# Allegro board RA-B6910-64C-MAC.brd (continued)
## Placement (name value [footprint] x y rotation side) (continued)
C1262  10uF/6.3V  [C0402]  211.55 147.82 180 bottom
C1263  10uF/6.3V  [C0402]  211.55 146.82 0 bottom
C1264  10uF/6.3V  [C0402]  211.55 145.82 0 bottom
C1265  10uF/6.3V  [C0402]  211.55 144.82 0 bottom
C1266  10uF/6.3V  [C0402]  211.55 143.82 180 bottom
C1267  10uF/6.3V  [C0402]  211.55 142.82 0 bottom
C1268  10uF/6.3V  [C0402]  211.55 141.82 180 bottom
C1269  10uF/6.3V  [C0402]  211.55 140.82 0 bottom
C2058  104  [C0603]  405.83 95.12 90 top
C2059  104  [C0603]  405.45 91.44 270 bottom
C2061  104  [C0603]  400.75 79.88 270 top
C2062  104  [C0603]  404.3 95.12 90 top
C2063  104  [C0603]  402.27 79.88 270 top
C2066  0.1uF/25V  [C0402]  413.45 53.59 0 bottom
C2067  102/2KV  [C2220]  419.04 32.51 90 bottom
C2068  0.1uF/25V  [C0402]  410.78 53.59 180 bottom
C2069  0.1uF/25V  [C0402]  407.1 53.59 180 bottom
C2070  0.1uF/25V  [C0402]  403.16 53.59 180 bottom
C2071  0.1uF/25V  [C0402]  410.27 56 270 bottom
C2072  0.1uF/25V  [C0402]  402.65 56 270 bottom
C2075  0.1uF/25V  [C0402]  202.63 172.59 90 bottom
C2076  0.1uF/25V  [C0402]  201.49 172.59 90 bottom
C2077  0.1uF/25V  [C0402]  208.09 179.96 90 top
C2078  0.1uF/25V  [C0402]  206.95 179.96 90 top
C2079  0.1uF/25V  [C0402]  197.8 179.96 90 top
C2080  0.1uF/25V  [C0402]  198.95 179.96 90 top
C2081  0.1uF/25V  [C0402]  195.14 179.96 90 top
C2082  0.1uF/25V  [C0402]  196.28 179.96 90 top
C2109  10uF/25V  [C0805]  59.75 205.99 270 bottom
C2110  104  [C0603]  20.38 205.74 270 bottom
C2116  100uF/6.3V  [C1206]  327.98 197.99 0 bottom
C2117  100uF/6.3V  [C1206]  328.1 186.94 0 bottom
C2147  22uF/6.3V  [C0603]  28.13 102.61 0 top
C2148  0.1uF/25V  [C0402]  8.06 87.25 180 bottom
C2149  22uF/6.3V  [C0603]  13.4 76.32 0 top
C2150  0.1uF/25V  [C0402]  13.4 74.55 180 top
C2151  22uF/6.3V  [C0603]  32.58 102.61 180 top
C2152  0.1uF/25V  [C0402]  8.06 86.23 180 bottom
C2153  22uF/6.3V  [C0603]  8.95 82.17 180 top
C2154  0.1uF/25V  [C0402]  8.95 80.39 0 top
C2155  22uF/6.3V  [C0603]  13.4 86.74 180 top
C2156  0.1uF/25V  [C0402]  49.97 91.56 0 bottom
C2157  22uF/6.3V  [C0603]  45.4 79.63 180 top
C2158  0.1uF/25V  [C0402]  45.4 77.85 0 top
C2159  22uF/6.3V  [C0603]  8.95 86.74 0 top
C2160  0.1uF/25V  [C0402]  45.53 91.69 180 bottom
C2161  22uF/6.3V  [C0603]  32.7 98.04 0 top
C2162  0.1uF/25V  [C0402]  35.12 90.68 180 top
C2163  22uF/6.3V  [C0603]  45.4 85.47 180 bottom
C2164  0.1uF/25V  [C0402]  45.4 83.69 0 bottom
C2165  22uF/6.3V  [C0603]  32.7 92.2 0 top
C2166  0.1uF/25V  [C0402]  32.58 90.42 180 top
C2167  22uF/6.3V  [C0603]  13.4 82.17 0 bottom
C2168  0.1uF/25V  [C0402]  13.4 80.39 180 bottom
C2169  22uF/6.3V  [C0603]  8.95 76.32 180 bottom
C2170  0.1uF/25V  [C0402]  8.95 74.55 0 bottom
C2171  22uF/6.3V  [C0603]  49.97 79.63 0 bottom
C2172  0.1uF/25V  [C0402]  49.97 77.85 180 bottom
C2173  22uF/6.3V  [C0603]  49.97 84.2 0 top
C2174  22uF/6.3V  [C0603]  28.13 92.2 180 bottom
C2175  0.1uF/25V  [C0402]  28.13 90.42 0 bottom
C2176  22uF/6.3V  [C0603]  28.13 98.04 180 bottom
C2177  0.1uF/25V  [C0402]  28.13 96.26 0 bottom
C2178  0.1uF/25V  [C0402]  52.77 84.07 90 top
C2179  22uF/6.3V  [C0603]  50.1 90.04 180 bottom
C2180  0.1uF/25V  [C0402]  28.26 103.88 180 bottom
C2181  22uF/6.3V  [C0603]  8.95 82.17 180 bottom
C2182  0.1uF/25V  [C0402]  8.95 80.39 0 bottom
C2183  22uF/6.3V  [C0603]  13.4 86.74 180 bottom
C2184  0.1uF/25V  [C0402]  28.26 102.61 180 bottom
C2185  22uF/6.3V  [C0603]  13.4 76.32 0 bottom
C2186  22uF/6.3V  [C0603]  32.96 102.49 180 bottom
C2187  0.1uF/25V  [C0402]  37.4 97.79 180 bottom
C2188  22uF/6.3V  [C0603]  32.7 98.04 0 bottom
C2189  0.1uF/25V  [C0402]  35.12 90.68 180 bottom
C2190  22uF/6.3V  [C0603]  45.66 90.04 0 bottom
C2191  0.1uF/25V  [C0402]  37.4 96.64 180 bottom
C2192  22uF/6.3V  [C0603]  45.4 79.63 180 bottom
C2193  0.1uF/25V  [C0402]  45.4 77.85 0 bottom
C2194  0.1uF/25V  [C0402]  13.4 74.55 180 bottom
C2195  22uF/6.3V  [C0603]  8.95 76.32 180 top
C2196  0.1uF/25V  [C0402]  8.95 74.55 0 top
C2197  22uF/6.3V  [C0603]  13.4 82.17 0 top
C2198  0.1uF/25V  [C0402]  13.4 80.39 180 top
C2199  22uF/6.3V  [C0603]  32.7 92.2 0 bottom
C2200  0.1uF/25V  [C0402]  32.7 90.42 180 bottom
C2201  22uF/6.3V  [C0603]  37.91 92.2 180 bottom
C2202  0.1uF/25V  [C0402]  37.66 90.42 0 bottom
C2203  22uF/6.3V  [C0603]  28.13 92.2 180 top
C2204  22uF/6.3V  [C0603]  49.97 85.47 0 bottom
C2205  0.1uF/25V  [C0402]  28.13 90.42 0 top
C2206  22uF/6.3V  [C0603]  28.13 98.04 180 top
C2207  0.1uF/25V  [C0402]  28.13 96.26 0 top
C2208  0.1uF/25V  [C0402]  49.97 83.69 180 bottom
C2209  22uF/6.3V  [C0603]  49.97 79.63 0 top
C2210  0.1uF/25V  [C0402]  49.97 77.85 180 top
C2211  22uF/6.3V  [C0603]  63.18 90.04 0 bottom
C2212  0.1uF/25V  [C0402]  75.63 89.53 180 bottom
C2213  22uF/6.3V  [C0603]  89.6 79.63 180 top
C2214  0.1uF/25V  [C0402]  88.71 77.85 0 top
C2215  22uF/6.3V  [C0603]  76.39 90.04 0 top
C2216  0.1uF/25V  [C0402]  94.93 90.68 0 bottom
C2217  22uF/6.3V  [C0603]  80.84 90.04 180 bottom
C2218  0.1uF/25V  [C0402]  88.84 89.66 180 bottom
C2219  22uF/6.3V  [C0603]  67.63 79.63 0 bottom
C2220  0.1uF/25V  [C0402]  67.63 77.85 180 bottom
C2221  22uF/6.3V  [C0603]  67.63 92.33 180 bottom
C2222  0.1uF/25V  [C0402]  75.63 90.55 180 bottom
C2223  22uF/6.3V  [C0603]  80.84 79.63 0 top
C2224  22uF/6.3V  [C0603]  63.18 79.63 180 bottom
C2225  0.1uF/25V  [C0402]  63.18 77.85 0 bottom
C2226  0.1uF/25V  [C0402]  80.84 77.85 180 top
C2227  22uF/6.3V  [C0603]  67.63 85.47 0 top
C2228  0.1uF/25V  [C0402]  67.63 83.69 180 top
C2229  22uF/6.3V  [C0603]  63.18 85.47 180 bottom
C2230  0.1uF/25V  [C0402]  63.18 83.69 0 bottom
C2231  22uF/6.3V  [C0603]  89.6 85.47 180 top
C2232  0.1uF/25V  [C0402]  89.6 83.69 0 top
C2233  22uF/6.3V  [C0603]  80.84 85.47 0 top
C2234  0.1uF/25V  [C0402]  80.84 83.69 180 top
C2235  22uF/6.3V  [C0603]  94.17 85.47 0 top
C2236  0.1uF/25V  [C0402]  94.17 83.69 180 top
C2237  22uF/6.3V  [C0603]  94.17 79.63 0 top
C2238  22uF/6.3V  [C0603]  76.39 79.63 180 bottom
C2239  0.1uF/25V  [C0402]  76.39 77.85 0 bottom
C2240  22uF/6.3V  [C0603]  76.39 85.47 180 bottom
C2241  0.1uF/25V  [C0402]  95.19 77.85 180 top
C2242  0.1uF/25V  [C0402]  76.39 83.69 0 bottom
C2243  22uF/6.3V  [C0603]  80.84 90.04 180 top
C2244  0.1uF/25V  [C0402]  88.84 90.68 180 bottom
C2245  22uF/6.3V  [C0603]  80.84 79.63 0 bottom
C2246  0.1uF/25V  [C0402]  80.84 77.85 180 bottom
C2247  22uF/6.3V  [C0603]  94.17 90.04 180 top
C2248  22uF/6.3V  [C0603]  89.6 90.04 0 top
C2249  0.1uF/25V  [C0402]  62.17 91.95 180 bottom
C2250  22uF/6.3V  [C0603]  63.18 79.63 180 top
C2251  0.1uF/25V  [C0402]  63.18 77.85 0 top
C2252  22uF/6.3V  [C0603]  67.63 90.04 180 bottom
C2253  0.1uF/25V  [C0402]  94.93 89.66 0 bottom
C2254  0.1uF/25V  [C0402]  62.17 92.96 180 bottom
C2255  22uF/6.3V  [C0603]  67.63 79.63 0 top
C2256  22uF/6.3V  [C0603]  89.6 79.63 180 bottom
C2257  0.1uF/25V  [C0402]  88.71 77.85 0 bottom
C2258  0.1uF/25V  [C0402]  67.63 77.85 180 top
C2259  22uF/6.3V  [C0603]  63.18 85.47 180 top
C2260  22uF/6.3V  [C0603]  80.84 85.47 0 bottom
C2261  0.1uF/25V  [C0402]  80.84 83.69 180 bottom
C2262  22uF/6.3V  [C0603]  89.6 85.47 180 bottom
C2263  0.1uF/25V  [C0402]  89.6 83.69 0 bottom
C2264  0.1uF/25V  [C0402]  63.18 83.69 0 top
C2265  22uF/6.3V  [C0603]  67.63 85.47 0 bottom
C2266  0.1uF/25V  [C0402]  67.63 83.69 180 bottom
C2267  22uF/6.3V  [C0603]  98.74 85.47 180 bottom
C2268  0.1uF/25V  [C0402]  98.74 83.69 0 bottom
C2269  22uF/6.3V  [C0603]  94.17 85.47 0 bottom
C2270  0.1uF/25V  [C0402]  94.17 83.69 180 bottom
C2271  22uF/6.3V  [C0603]  76.39 85.47 180 top
C2272  0.1uF/25V  [C0402]  76.39 83.69 0 top
C2273  22uF/6.3V  [C0603]  76.39 79.63 180 top
C2274  0.1uF/25V  [C0402]  76.39 77.85 0 top
C2275  22uF/6.3V  [C0603]  117.41 90.04 180 top
C2276  0.1uF/25V  [C0402]  112.2 90.55 180 bottom
C2277  22uF/6.3V  [C0603]  139.38 85.47 180 bottom
C2278  0.1uF/25V  [C0402]  139.38 83.69 0 bottom
C2279  22uF/6.3V  [C0603]  139.38 90.04 0 top
C2280  0.1uF/25V  [C0402]  112.2 89.53 180 bottom
C2281  22uF/6.3V  [C0603]  130.62 85.47 0 top
C2282  0.1uF/25V  [C0402]  130.62 83.69 180 top
C2283  22uF/6.3V  [C0603]  130.62 90.04 180 bottom
C2284  0.1uF/25V  [C0402]  138.62 90.68 180 bottom
C2285  22uF/6.3V  [C0603]  117.41 79.63 0 bottom
C2286  0.1uF/25V  [C0402]  117.41 77.85 180 bottom
C2287  22uF/6.3V  [C0603]  130.62 90.04 180 top
C2288  0.1uF/25V  [C0402]  138.62 89.66 180 bottom
C2289  22uF/6.3V  [C0603]  108.52 85.47 0 bottom
C2290  0.1uF/25V  [C0402]  108.52 83.69 180 bottom
C2291  22uF/6.3V  [C0603]  139.38 79.63 180 bottom
C2292  0.1uF/25V  [C0402]  139.38 77.85 0 bottom
C2293  22uF/6.3V  [C0603]  117.41 85.47 0 top
C2294  0.1uF/25V  [C0402]  117.41 83.69 180 top
C2295  22uF/6.3V  [C0603]  112.97 85.47 180 bottom
C2296  0.1uF/25V  [C0402]  112.97 83.69 0 bottom
C2297  22uF/6.3V  [C0603]  130.62 79.63 0 top
C2298  0.1uF/25V  [C0402]  130.62 77.85 180 top
C2299  22uF/6.3V  [C0603]  126.17 79.63 180 bottom
C2300  22uF/6.3V  [C0603]  143.95 79.63 0 bottom
C2301  0.1uF/25V  [C0402]  143.95 77.85 180 bottom
C2302  22uF/6.3V  [C0603]  138.87 93.47 270 bottom
C2303  0.1uF/25V  [C0402]  140.65 92.96 90 bottom
C2304  0.1uF/25V  [C0402]  126.17 77.85 0 bottom
C2305  22uF/6.3V  [C0603]  126.17 85.47 180 bottom
C2306  0.1uF/25V  [C0402]  126.17 83.69 0 bottom
C2307  22uF/6.3V  [C0603]  126.17 90.04 0 top
C2308  0.1uF/25V  [C0402]  125.41 90.55 180 bottom
C2309  22uF/6.3V  [C0603]  112.97 90.04 0 top
C2310  0.1uF/25V  [C0402]  125.41 89.53 180 bottom
C2311  22uF/6.3V  [C0603]  112.97 79.63 180 top
C2312  0.1uF/25V  [C0402]  112.97 77.85 0 top
C2313  22uF/6.3V  [C0603]  117.41 90.04 180 bottom
C2314  0.1uF/25V  [C0402]  133.67 92.33 270 bottom
C2315  22uF/6.3V  [C0603]  117.41 79.63 0 top
C2316  22uF/6.3V  [C0603]  130.62 85.47 0 bottom
C2317  0.1uF/25V  [C0402]  130.62 83.69 180 bottom
C2318  22uF/6.3V  [C0603]  143.95 90.04 180 top
C2319  0.1uF/25V  [C0402]  134.81 92.33 270 bottom
C2320  22uF/6.3V  [C0603]  139.38 85.47 180 top
C2321  0.1uF/25V  [C0402]  139.38 83.69 0 top
C2322  0.1uF/25V  [C0402]  117.41 77.85 180 top
C2323  22uF/6.3V  [C0603]  112.97 85.47 180 top
C2324  0.1uF/25V  [C0402]  112.97 83.69 0 top
C2325  22uF/6.3V  [C0603]  117.41 85.47 0 bottom
C2326  0.1uF/25V  [C0402]  117.41 83.69 180 bottom
C2327  22uF/6.3V  [C0603]  130.62 79.63 0 bottom
C2328  0.1uF/25V  [C0402]  130.62 77.85 180 bottom
C2329  22uF/6.3V  [C0603]  139.38 79.63 180 top
C2330  0.1uF/25V  [C0402]  139.38 77.85 0 top
C2331  22uF/6.3V  [C0603]  143.95 85.47 0 top
C2332  22uF/6.3V  [C0603]  126.17 85.47 180 top
C2333  0.1uF/25V  [C0402]  126.17 83.69 0 top
C2334  22uF/6.3V  [C0603]  126.17 79.63 180 top
C2335  0.1uF/25V  [C0402]  126.17 77.85 0 top
C2336  0.1uF/25V  [C0402]  143.95 83.69 180 top
C2337  22uF/6.3V  [C0603]  143.95 79.63 0 top
C2338  0.1uF/25V  [C0402]  143.95 77.85 180 top
C2339  22uF/6.3V  [C0603]  174.82 90.04 180 top
C2340  0.1uF/25V  [C0402]  182.82 89.66 180 bottom
C2341  22uF/6.3V  [C0603]  174.82 90.04 180 bottom
C2342  0.1uF/25V  [C0402]  182.82 90.68 180 bottom
C2343  22uF/6.3V  [C0603]  183.58 79.63 180 top
C2344  0.1uF/25V  [C0402]  183.58 77.85 0 top
C2345  22uF/6.3V  [C0603]  170.37 90.04 0 top
C2346  0.1uF/25V  [C0402]  188.91 89.66 0 bottom
C2347  22uF/6.3V  [C0603]  174.82 79.63 0 top
C2348  22uF/6.3V  [C0603]  161.61 79.63 0 bottom
C2349  0.1uF/25V  [C0402]  161.61 77.85 180 bottom
C2350  22uF/6.3V  [C0603]  161.61 90.04 180 top
C2351  0.1uF/25V  [C0402]  188.91 90.68 0 bottom
C2352  22uF/6.3V  [C0603]  157.16 79.63 180 bottom
C2353  0.1uF/25V  [C0402]  157.16 77.85 0 bottom
C2354  0.1uF/25V  [C0402]  174.82 77.85 180 top
C2355  22uF/6.3V  [C0603]  183.58 85.47 180 top
C2356  0.1uF/25V  [C0402]  183.58 83.69 0 top
C2357  22uF/6.3V  [C0603]  174.82 85.47 0 top
C2358  22uF/6.3V  [C0603]  161.61 85.47 0 top
C2359  0.1uF/25V  [C0402]  161.61 83.69 180 top
C2360  0.1uF/25V  [C0402]  174.82 83.69 180 top
C2361  22uF/6.3V  [C0603]  138.87 98.17 270 bottom
C2362  0.1uF/25V  [C0402]  140.65 97.66 90 bottom
C2363  22uF/6.3V  [C0603]  192.72 85.47 180 bottom
C2364  0.1uF/25V  [C0402]  192.21 83.69 0 bottom
C2365  22uF/6.3V  [C0603]  188.15 85.47 0 bottom
C2366  22uF/6.3V  [C0603]  170.37 79.63 180 bottom
C2367  0.1uF/25V  [C0402]  170.37 77.85 0 bottom
C2368  22uF/6.3V  [C0603]  170.37 85.47 180 bottom
C2369  0.1uF/25V  [C0402]  188.15 83.69 180 bottom
C2370  0.1uF/25V  [C0402]  170.37 83.69 0 bottom
C2371  22uF/6.3V  [C0603]  188.15 90.04 180 top
C2372  0.1uF/25V  [C0402]  133.67 97.03 270 bottom
C2373  22uF/6.3V  [C0603]  174.82 79.63 0 bottom
C2374  0.1uF/25V  [C0402]  174.82 77.85 180 bottom
C2375  22uF/6.3V  [C0603]  183.58 90.04 0 top
C2376  0.1uF/25V  [C0402]  169.61 90.55 180 bottom
C2377  22uF/6.3V  [C0603]  161.61 96.9 180 top
C2378  0.1uF/25V  [C0402]  134.81 97.03 270 bottom
C2379  22uF/6.3V  [C0603]  157.16 79.63 180 top
C2380  0.1uF/25V  [C0402]  157.16 77.85 0 top
C2381  22uF/6.3V  [C0603]  161.61 92.33 180 top
C2382  0.1uF/25V  [C0402]  169.61 89.53 180 bottom
C2383  22uF/6.3V  [C0603]  161.61 79.63 0 top
C2384  22uF/6.3V  [C0603]  183.58 79.63 180 bottom
C2385  0.1uF/25V  [C0402]  183.58 77.85 0 bottom
C2386  0.1uF/25V  [C0402]  161.61 77.85 180 top
C2387  22uF/6.3V  [C0603]  174.82 85.47 0 bottom
C2388  0.1uF/25V  [C0402]  174.82 83.69 180 bottom
C2389  22uF/6.3V  [C0603]  157.16 85.47 180 top
C2390  0.1uF/25V  [C0402]  157.16 83.69 0 top
C2391  22uF/6.3V  [C0603]  166.05 92.2 0 top
C2392  0.1uF/25V  [C0402]  165.8 90.68 180 top
C2393  22uF/6.3V  [C0603]  183.58 85.47 180 bottom
C2394  0.1uF/25V  [C0402]  183.58 83.69 0 bottom
C2395  22uF/6.3V  [C0603]  170.37 85.47 180 top
C2396  0.1uF/25V  [C0402]  170.37 83.69 0 top
C2397  22uF/6.3V  [C0603]  188.15 85.47 0 top
C2398  0.1uF/25V  [C0402]  188.15 83.69 180 top
C2399  22uF/6.3V  [C0603]  188.15 79.63 0 top
C2400  22uF/6.3V  [C0603]  170.37 79.63 180 top
C2401  0.1uF/25V  [C0402]  170.37 77.85 0 top
C2402  0.1uF/25V  [C0402]  188.15 77.85 180 top
C2403  22uF/6.3V  [C0603]  235.78 92.45 180 top
C2404  0.1uF/25V  [C0402]  251.9 97.03 90 top
C2405  22uF/6.3V  [C0603]  233.36 79.63 180 top
C2406  22uF/6.3V  [C0603]  206.95 90.04 0 top
C2407  0.1uF/25V  [C0402]  200.6 89.79 180 bottom
C2408  22uF/6.3V  [C0603]  211.39 79.63 0 top
C2409  0.1uF/25V  [C0402]  211.39 77.85 180 top
C2410  22uF/6.3V  [C0603]  233.36 90.04 0 top
C2411  0.1uF/25V  [C0402]  252.92 97.03 90 top
C2412  22uF/6.3V  [C0603]  206.95 85.47 180 top
C2413  0.1uF/25V  [C0402]  233.36 77.85 0 top
C2414  22uF/6.3V  [C0603]  211.39 90.04 180 bottom
C2415  0.1uF/25V  [C0402]  200.6 90.8 180 bottom
C2416  22uF/6.3V  [C0603]  224.6 85.47 0 top
C2417  0.1uF/25V  [C0402]  206.95 83.69 0 top
C2418  0.1uF/25V  [C0402]  224.6 83.69 180 top
C2419  22uF/6.3V  [C0603]  211.39 85.47 0 bottom
C2420  0.1uF/25V  [C0402]  211.39 83.69 180 bottom
C2421  22uF/6.3V  [C0603]  201.99 85.72 180 bottom
C2422  0.1uF/25V  [C0402]  202.12 84.2 0 bottom
C2423  22uF/6.3V  [C0603]  230.19 92.33 180 bottom
C2424  0.1uF/25V  [C0402]  233.36 83.69 0 bottom
C2425  22uF/6.3V  [C0603]  224.6 79.63 0 top
C2426  0.1uF/25V  [C0402]  224.6 77.85 180 top
C2427  22uF/6.3V  [C0603]  220.15 79.63 180 bottom
C2428  0.1uF/25V  [C0402]  220.15 77.85 0 bottom
C2429  22uF/6.3V  [C0603]  220.15 85.47 180 bottom
C2430  0.1uF/25V  [C0402]  220.15 83.69 0 bottom
C2431  22uF/6.3V  [C0603]  237.93 79.63 0 bottom
C2432  0.1uF/25V  [C0402]  237.93 77.85 180 bottom
C2433  22uF/6.3V  [C0603]  237.93 85.47 0 top
C2434  0.1uF/25V  [C0402]  237.93 83.69 180 top
C2435  22uF/6.3V  [C0603]  224.6 90.04 180 top
C2436  0.1uF/25V  [C0402]  254.95 97.03 90 top
C2437  22uF/6.3V  [C0603]  224.6 85.47 0 bottom
C2438  0.1uF/25V  [C0402]  224.6 83.69 180 bottom
C2439  22uF/6.3V  [C0603]  211.39 90.04 180 top
C2440  0.1uF/25V  [C0402]  253.94 97.03 90 top
C2441  22uF/6.3V  [C0603]  233.36 79.63 180 bottom
C2442  22uF/6.3V  [C0603]  224.6 90.04 180 bottom
C2443  0.1uF/25V  [C0402]  219.39 89.53 180 bottom
C2444  22uF/6.3V  [C0603]  206.95 85.47 180 bottom
C2445  0.1uF/25V  [C0402]  206.95 83.69 0 bottom
C2446  22uF/6.3V  [C0603]  220.15 90.04 0 top
C2447  0.1uF/25V  [C0402]  219.39 90.55 180 bottom
C2448  22uF/6.3V  [C0603]  211.39 79.63 0 bottom
C2449  0.1uF/25V  [C0402]  211.39 77.85 180 bottom
C2450  0.1uF/25V  [C0402]  233.36 77.85 0 bottom
C2451  22uF/6.3V  [C0603]  206.95 79.63 180 top
C2452  0.1uF/25V  [C0402]  206.95 77.85 0 top
C2453  22uF/6.3V  [C0603]  211.39 85.47 0 top
C2454  22uF/6.3V  [C0603]  224.6 79.63 0 bottom
C2455  0.1uF/25V  [C0402]  224.6 77.85 180 bottom
C2456  22uF/6.3V  [C0603]  233.36 85.47 180 top
C2457  0.1uF/25V  [C0402]  233.36 83.69 0 top
C2458  0.1uF/25V  [C0402]  211.39 83.69 180 top
C2459  22uF/6.3V  [C0603]  220.15 85.47 180 top
C2460  0.1uF/25V  [C0402]  220.15 83.69 0 top
C2461  22uF/6.3V  [C0603]  220.15 79.63 180 top
C2462  0.1uF/25V  [C0402]  220.15 77.85 0 top
C2463  22uF/6.3V  [C0603]  251.14 92.33 180 top
C2464  0.1uF/25V  [C0402]  237.93 83.69 180 bottom
C2465  22uF/6.3V  [C0603]  237.93 79.63 0 top
C2466  0.1uF/25V  [C0402]  237.93 77.85 180 top
C2467  22uF/6.3V  [C0603]  282.13 90.04 180 top
C2468  0.1uF/25V  [C0402]  281.62 91.82 0 top
C2469  22uF/6.3V  [C0603]  255.71 94.61 180 top
C2470  0.1uF/25V  [C0402]  279.46 91.82 180 top
C2471  22uF/6.3V  [C0603]  277.56 79.63 180 top
C2472  0.1uF/25V  [C0402]  277.56 77.85 0 top
C2473  22uF/6.3V  [C0603]  255.59 90.04 180 top
C2474  0.1uF/25V  [C0402]  263.59 90.55 180 bottom
C2475  22uF/6.3V  [C0603]  268.8 79.63 0 top
C2476  22uF/6.3V  [C0603]  255.59 79.63 0 bottom
C2477  0.1uF/25V  [C0402]  255.59 77.85 180 bottom
C2478  22uF/6.3V  [C0603]  264.35 90.04 0 top
C2479  0.1uF/25V  [C0402]  263.59 89.53 180 bottom
C2480  22uF/6.3V  [C0603]  251.14 79.63 180 bottom
C2481  0.1uF/25V  [C0402]  251.14 77.85 0 bottom
C2482  0.1uF/25V  [C0402]  268.8 77.85 180 top
C2483  22uF/6.3V  [C0603]  277.56 85.47 180 top
C2484  0.1uF/25V  [C0402]  277.56 83.69 0 top
C2485  22uF/6.3V  [C0603]  268.8 85.47 0 top
C2486  22uF/6.3V  [C0603]  255.59 85.47 0 top
C2487  0.1uF/25V  [C0402]  255.59 83.69 180 top
C2488  0.1uF/25V  [C0402]  268.8 83.69 180 top
C2489  22uF/6.3V  [C0603]  254.57 87.63 90 bottom
C2490  0.1uF/25V  [C0402]  251.14 83.69 0 bottom
C2491  22uF/6.3V  [C0603]  282.13 85.47 0 top
C2492  0.1uF/25V  [C0402]  282.13 83.69 180 top
C2493  22uF/6.3V  [C0603]  282.13 79.63 0 top
C2494  22uF/6.3V  [C0603]  264.35 79.63 180 bottom
C2495  0.1uF/25V  [C0402]  264.35 77.85 0 bottom
C2496  22uF/6.3V  [C0603]  264.35 85.47 180 bottom
C2497  0.1uF/25V  [C0402]  282.13 77.85 180 top
C2498  0.1uF/25V  [C0402]  264.35 83.69 0 bottom
C2499  22uF/6.3V  [C0603]  277.56 90.04 0 top
C2500  0.1uF/25V  [C0402]  219.39 91.95 180 bottom
C2501  22uF/6.3V  [C0603]  268.8 90.04 180 bottom
C2502  0.1uF/25V  [C0402]  276.8 92.83 180 top
C2503  22uF/6.3V  [C0603]  251.14 79.63 180 top
C2504  0.1uF/25V  [C0402]  251.14 77.85 0 top
C2505  22uF/6.3V  [C0603]  268.8 90.04 180 top
C2506  0.1uF/25V  [C0402]  276.8 91.82 180 top
C2507  22uF/6.3V  [C0603]  255.59 79.63 0 top
C2508  22uF/6.3V  [C0603]  268.8 79.63 0 bottom
C2509  0.1uF/25V  [C0402]  268.8 77.85 180 bottom
C2510  22uF/6.3V  [C0603]  251.14 90.04 0 top
C2511  0.1uF/25V  [C0402]  219.39 91.95 180 top
C2512  22uF/6.3V  [C0603]  277.56 79.63 180 bottom
C2513  0.1uF/25V  [C0402]  277.56 77.85 0 bottom
C2514  0.1uF/25V  [C0402]  255.59 77.85 180 top
C2515  22uF/6.3V  [C0603]  268.8 85.47 0 bottom
C2516  0.1uF/25V  [C0402]  268.8 83.69 180 bottom
C2517  22uF/6.3V  [C0603]  251.14 85.47 180 top
C2518  0.1uF/25V  [C0402]  251.14 83.69 0 top
C2519  22uF/6.3V  [C0603]  256.86 87.63 270 bottom
C2520  0.1uF/25V  [C0402]  255.59 83.69 180 bottom
C2521  22uF/6.3V  [C0603]  277.56 85.47 180 bottom
C2522  0.1uF/25V  [C0402]  277.56 83.69 0 bottom
C2523  22uF/6.3V  [C0603]  286.45 85.47 180 bottom
C2524  0.1uF/25V  [C0402]  286.45 83.69 0 bottom
C2525  22uF/6.3V  [C0603]  282.13 85.47 0 bottom
C2526  22uF/6.3V  [C0603]  264.35 85.47 180 top
C2527  0.1uF/25V  [C0402]  264.35 83.69 0 top
C2528  22uF/6.3V  [C0603]  264.35 79.63 180 top
C2529  0.1uF/25V  [C0402]  264.35 77.85 0 top
C2530  0.1uF/25V  [C0402]  282.13 83.69 180 bottom
C2531  22uF/6.3V  [C0603]  333.57 92.45 180 bottom
C2532  0.1uF/25V  [C0402]  328.23 90.68 180 bottom
C2533  22uF/6.3V  [C0603]  328.99 79.63 180 bottom
C2534  0.1uF/25V  [C0402]  328.99 77.85 0 bottom
C2535  22uF/6.3V  [C0603]  320.23 90.04 180 bottom
C2536  0.1uF/25V  [C0402]  287.72 90.42 90 top
C2537  22uF/6.3V  [C0603]  309.56 90.17 180 top
C2538  0.1uF/25V  [C0402]  328.23 89.66 180 bottom
C2539  22uF/6.3V  [C0603]  304.99 79.63 0 bottom
C2540  0.1uF/25V  [C0402]  303.85 77.85 180 bottom
C2541  22uF/6.3V  [C0603]  328.99 90.04 0 top
C2542  0.1uF/25V  [C0402]  334.33 89.66 0 bottom
C2543  22uF/6.3V  [C0603]  320.23 85.47 0 bottom
C2544  22uF/6.3V  [C0603]  286.45 85.47 180 top
C2545  0.1uF/25V  [C0402]  286.45 83.69 0 top
C2546  0.1uF/25V  [C0402]  320.23 83.69 180 bottom
C2547  22uF/6.3V  [C0603]  304.86 85.6 180 top
C2548  0.1uF/25V  [C0402]  304.86 83.82 0 top
C2549  22uF/6.3V  [C0603]  300.55 79.63 180 top
C2550  0.1uF/25V  [C0402]  299.4 77.85 0 top
C2551  22uF/6.3V  [C0603]  328.99 85.47 180 top
C2552  0.1uF/25V  [C0402]  328.99 83.69 0 top
C2553  22uF/6.3V  [C0603]  320.23 79.63 0 bottom
C2554  0.1uF/25V  [C0402]  320.23 77.85 180 bottom
C2555  22uF/6.3V  [C0603]  315.79 79.63 180 bottom
C2556  0.1uF/25V  [C0402]  315.79 77.85 0 bottom
C2557  22uF/6.3V  [C0603]  315.79 85.47 180 bottom
C2558  0.1uF/25V  [C0402]  315.79 83.69 0 bottom
C2559  22uF/6.3V  [C0603]  333.57 79.63 0 bottom
C2560  0.1uF/25V  [C0402]  331.53 77.85 180 bottom
C2561  22uF/6.3V  [C0603]  333.57 85.47 0 top
C2562  0.1uF/25V  [C0402]  333.57 83.69 180 top
C2563  22uF/6.3V  [C0603]  315.79 90.04 0 top
C2564  0.1uF/25V  [C0402]  315.02 89.53 180 bottom
C2565  22uF/6.3V  [C0603]  320.23 85.47 0 top
C2566  0.1uF/25V  [C0402]  320.23 83.69 180 top
C2567  22uF/6.3V  [C0603]  320.23 90.04 180 top
C2568  22uF/6.3V  [C0603]  293.56 88.9 180 top
C2569  0.1uF/25V  [C0402]  315.02 90.55 180 bottom
C2570  22uF/6.3V  [C0603]  300.29 85.6 180 top
C2571  0.1uF/25V  [C0402]  300.42 83.82 0 top
C2572  22uF/6.3V  [C0603]  333.57 90.04 180 top
C2573  0.1uF/25V  [C0402]  289.12 90.42 90 top
C2574  0.1uF/25V  [C0402]  334.33 90.68 0 bottom
C2575  22uF/6.3V  [C0603]  304.99 79.63 0 top
C2576  22uF/6.3V  [C0603]  328.99 79.63 180 top
C2577  0.1uF/25V  [C0402]  328.99 77.85 0 top
C2578  0.1uF/25V  [C0402]  303.85 77.85 180 top
C2579  22uF/6.3V  [C0603]  320.23 79.63 0 top
C2580  22uF/6.3V  [C0603]  293.56 84.33 0 top
C2581  0.1uF/25V  [C0402]  320.23 77.85 180 top
C2582  22uF/6.3V  [C0603]  328.99 85.47 180 bottom
C2583  0.1uF/25V  [C0402]  328.99 83.69 0 bottom
C2584  0.1uF/25V  [C0402]  296.48 84.2 90 top
C2585  22uF/6.3V  [C0603]  309.44 85.6 0 top
C2586  0.1uF/25V  [C0402]  309.44 83.82 180 top
C2587  22uF/6.3V  [C0603]  333.57 85.47 0 bottom
C2588  0.1uF/25V  [C0402]  333.57 83.69 180 bottom
C2589  22uF/6.3V  [C0603]  333.57 79.63 0 top
C2590  0.1uF/25V  [C0402]  331.53 77.85 180 top
C2591  22uF/6.3V  [C0603]  315.79 85.47 180 top
C2592  0.1uF/25V  [C0402]  315.79 83.69 0 top
C2593  22uF/6.3V  [C0603]  315.79 79.63 180 top
C2594  0.1uF/25V  [C0402]  315.79 77.85 0 top
C2595  22uF/6.3V  [C0603]  389.57 89.15 180 top
C2596  0.1uF/25V  [C0402]  390.33 89.79 0 bottom
C2597  22uF/6.3V  [C0603]  353 79.63 0 bottom
C2598  0.1uF/25V  [C0402]  353 77.85 180 bottom
C2599  22uF/6.3V  [C0603]  385 89.15 0 top
C2600  0.1uF/25V  [C0402]  390.33 88.77 0 bottom
C2601  22uF/6.3V  [C0603]  348.55 79.63 180 bottom
C2602  0.1uF/25V  [C0402]  347.41 77.85 0 bottom
C2603  22uF/6.3V  [C0603]  379.54 82.17 180 top
C2604  0.1uF/25V  [C0402]  384.24 89.79 180 bottom
C2605  22uF/6.3V  [C0603]  389.57 84.58 0 top
C2606  0.1uF/25V  [C0402]  389.57 82.8 180 top
C2607  22uF/6.3V  [C0603]  348.55 92.33 0 bottom
C2608  0.1uF/25V  [C0402]  348.55 95.12 180 bottom
C2609  22uF/6.3V  [C0603]  371.92 82.55 270 bottom
C2610  0.1uF/25V  [C0402]  370.52 82.29 90 bottom
C2611  22uF/6.3V  [C0603]  385 84.58 180 top
C2612  0.1uF/25V  [C0402]  385 82.8 0 top
C2613  22uF/6.3V  [C0603]  353 85.47 0 top
C2614  0.1uF/25V  [C0402]  353 83.69 180 top
C2615  22uF/6.3V  [C0603]  348.55 85.47 180 bottom
C2616  0.1uF/25V  [C0402]  348.55 83.69 0 bottom
C2617  22uF/6.3V  [C0603]  371.92 82.55 270 top
C2618  0.1uF/25V  [C0402]  370.52 82.29 90 top
C2619  22uF/6.3V  [C0603]  385 78.74 180 top
C2620  22uF/6.3V  [C0603]  361.76 79.63 180 bottom
C2621  0.1uF/25V  [C0402]  385 76.96 0 top
C2622  22uF/6.3V  [C0603]  389.57 78.74 0 top
C2623  0.1uF/25V  [C0402]  389.57 76.96 180 top
C2624  0.1uF/25V  [C0402]  361.76 77.85 0 bottom
C2625  22uF/6.3V  [C0603]  366.2 79.63 0 top
C2626  0.1uF/25V  [C0402]  366.2 77.85 180 top
C2627  22uF/6.3V  [C0603]  353 92.33 180 bottom
C2628  0.1uF/25V  [C0402]  355.66 88.01 180 top
C2629  22uF/6.3V  [C0603]  353 90.04 180 bottom
C2630  0.1uF/25V  [C0402]  355.66 86.99 180 top
C2631  22uF/6.3V  [C0603]  348.55 79.63 180 top
C2632  0.1uF/25V  [C0402]  347.41 77.85 0 top
C2633  22uF/6.3V  [C0603]  366.71 84.71 180 top
C2634  0.1uF/25V  [C0402]  384.24 88.77 180 bottom
C2635  22uF/6.3V  [C0603]  353 79.63 0 top
C2636  22uF/6.3V  [C0603]  366.2 79.63 0 bottom
C2637  0.1uF/25V  [C0402]  366.2 77.85 180 bottom
C2638  22uF/6.3V  [C0603]  385 97.28 0 top
C2639  0.1uF/25V  [C0402]  348.55 94.1 180 bottom
C2640  22uF/6.3V  [C0603]  389.57 84.58 0 bottom
C2641  0.1uF/25V  [C0402]  389.57 82.8 180 bottom
C2642  0.1uF/25V  [C0402]  353 77.85 180 top
C2643  22uF/6.3V  [C0603]  348.55 85.47 180 top
C2644  0.1uF/25V  [C0402]  348.55 83.69 0 top
C2645  22uF/6.3V  [C0603]  353 85.47 0 bottom
C2646  0.1uF/25V  [C0402]  353 83.69 180 bottom
C2647  22uF/6.3V  [C0603]  385 92.71 180 top
C2648  0.1uF/25V  [C0402]  385 90.93 0 top
C2649  22uF/6.3V  [C0603]  385 84.58 180 bottom
C2650  0.1uF/25V  [C0402]  385 82.8 0 bottom
C2651  22uF/6.3V  [C0603]  389.57 78.74 0 bottom
C2652  0.1uF/25V  [C0402]  389.57 76.96 180 bottom
C2653  22uF/6.3V  [C0603]  385 78.74 180 bottom
C2654  22uF/6.3V  [C0603]  359.22 84.2 0 top
C2655  0.1uF/25V  [C0402]  363.66 85.34 90 top
C2656  22uF/6.3V  [C0603]  361.76 79.63 180 top
C2657  0.1uF/25V  [C0402]  361.76 77.85 0 top
C2658  0.1uF/25V  [C0402]  385 76.96 0 bottom
C2659  47uF/6.3V  [C0805]  143.32 114.17 180 top
C2660  0.1uF/25V  [C0402]  203.04 170.34 270 bottom
C2661  0.1uF/25V  [C0402]  225.59 152.85 180 bottom
C2662  10uF/6.3V  [C0402]  191.55 143.82 0 bottom
C2663  10uF/6.3V  [C0402]  193.55 134.83 0 bottom
C2664  0.1uF/25V  [C0402]  229.55 121.83 0 bottom
C2665  22uF/6.3V  [C0603]  197.29 96.64 180 top
C2666  0.1uF/25V  [C0402]  224.47 200.15 90 top
C2667  22uF/6.3V  [C0603]  169.48 101.22 180 top
C2668  0.1uF/25V  [C0402]  187.53 110.86 0 bottom
C2669  10uF/6.3V  [C0402]  257.11 122.93 0 top
C2671  10uF/6.3V  [C0402]  257.24 166.24 0 top
C2672  47uF/6.3V  [C0805]  143.32 109.6 180 top
C2673  47uF/6.3V  [C0805]  143.32 105.03 180 top
C2674  0.1uF/25V  [C0402]  168.57 125.85 0 bottom
C2675  47uF/6.3V  [C0805]  148.02 170.43 0 top
C2676  0.1uF/25V  [C0402]  167.2 190.88 270 top
C2677  10uF/6.3V  [C0402]  201.54 140.83 0 bottom
C2678  0.1uF/25V  [C0402]  207.57 153.85 0 bottom
C2679  0.1uF/25V  [C0402]  192.03 170.33 270 bottom
C2680  10uF/6.3V  [C0402]  201.54 132.83 0 bottom
C2681  0.1uF/25V  [C0402]  215.04 167.36 90 bottom
C2682  0.1uF/25V  [C0402]  191.55 124.83 0 bottom
C2683  0.1uF/25V  [C0402]  224.09 101.72 0 top
C2684  0.1uF/25V  [C0402]  181.53 120.84 0 bottom
C2685  0.1uF/25V  [C0402]  187.55 125.83 0 bottom
C2686  47uF/6.3V  [C0805]  143.57 151 180 top
C2687  22uF/6.3V  [C0603]  235.65 150.11 270 top
C2688  0.1uF/25V  [C0402]  216.04 171.35 270 bottom
C2689  0.1uF/25V  [C0402]  217.56 153.84 0 bottom
C2690  0.1uF/25V  [C0402]  168.53 140.85 0 bottom
C2691  47uF/6.3V  [C0805]  142.81 136.01 180 top
C2692  0.1uF/25V  [C0402]  207.02 168.32 90 bottom
C2693  22uF/6.3V  [C0603]  154.98 154.79 0 bottom
C2694  0.1uF/25V  [C0402]  225.56 162.91 180 bottom
C2695  0.1uF/25V  [C0402]  199.56 121.84 0 bottom
C2696  0.1uF/25V  [C0402]  183.54 152.83 0 bottom
C2697  47uF/6.3V  [C0805]  143.32 125.6 180 top
C2698  47uF/6.3V  [C0805]  143.32 123.31 180 top
C2699  22uF/6.3V  [C0603]  242.51 137.79 270 top
C2700  10uF/6.3V  [C0402]  205.55 144.82 0 bottom
C2701  10uF/6.3V  [C0402]  205.55 147.82 0 bottom
C2702  47uF/6.3V  [C0805]  143.32 118.74 180 top
C2703  0.1uF/25V  [C0402]  165.56 170.82 0 bottom
C2704  0.1uF/25V  [C0402]  221.56 167.82 0 bottom
C2705  0.1uF/25V  [C0402]  181.55 137.87 0 bottom
C2706  0.1uF/25V  [C0402]  229.55 131.82 0 bottom
C2707  10uF/6.3V  [C0402]  205.55 132.82 0 bottom
C2708  47uF/6.3V  [C0805]  257.11 148.08 0 top
C2710  10uF/6.3V  [C0402]  203.54 130.83 0 bottom
C2712  0.1uF/25V  [C0402]  201.03 170.36 270 bottom
C2713  0.1uF/25V  [C0402]  181.54 151.83 0 bottom
C2714  0.1uF/25V  [C0402]  211.56 120.84 180 bottom
C2715  10uF/6.3V  [C0402]  199.54 142.83 0 bottom
C2716  0.1uF/25V  [C0402]  213.55 126.82 0 bottom
C2717  0.1uF/25V  [C0402]  213.55 130.82 0 bottom
C2719  0.1uF/25V  [C0402]  153.05 127.25 90 top
C2720  0.1uF/25V  [C0402]  195.55 122.84 0 bottom
C2721  103  [C0402]  155.51 154.18 0 top
C2722  22uF/6.3V  [C0603]  240.22 150.11 270 top
C2723  0.1uF/25V  [C0402]  162.24 178.43 270 top
C2724  10uF/6.3V  [C0402]  201.54 145.83 180 bottom
C2725  10uF/6.3V  [C0402]  205.55 135.82 0 bottom
C2726  10uF/6.3V  [C0402]  142.81 129.03 180 top
C2727  22uF/6.3V  [C0603]  184.47 101.22 180 top
C2728  0.1uF/25V  [C0402]  199.06 162.35 90 bottom
C2729  0.1uF/25V  [C0402]  165.54 107.82 0 bottom
C2730  47uF/6.3V  [C0805]  257.11 118.36 0 top
C2731  0.1uF/25V  [C0402]  229.04 171.32 90 bottom
C2732  47uF/6.3V  [C0805]  257.11 116.08 0 top
C2733  47uF/6.3V  [C0805]  143.57 144.14 180 top
C2734  0.1uF/25V  [C0402]  212.05 167.36 270 bottom
C2735  22uF/6.3V  [C0603]  159.45 133.09 270 top
C2736  47uF/6.3V  [C0805]  142.81 138.3 180 top
C2737  0.1uF/25V  [C0402]  218.55 172.84 180 bottom
C2738  0.1uF/25V  [C0402]  165.56 158.82 0 bottom
C2739  0.1uF/25V  [C0402]  199.54 153.83 180 bottom
C2740  10uF/6.3V  [C0402]  207.55 136.82 180 bottom
C2741  10uF/6.3V  [C0402]  142.81 133.73 180 top
C2742  0.1uF/25V  [C0402]  213.55 146.82 0 bottom
C2743  0.1uF/25V  [C0402]  225.54 137.85 180 bottom
C2744  0.1uF/25V  [C0402]  223.53 171.85 0 bottom
C2745  47uF/6.3V  [C0805]  143.57 170.43 180 top
C2746  0.1uF/25V  [C0402]  238.44 131.82 90 top
C2748  10uF/6.3V  [C0402]  209.55 126.82 0 bottom
C2749  10uF/6.3V  [C0402]  142.81 131.44 180 top
C2750  47uF/6.3V  [C0805]  143.57 165.86 180 top
C2751  0.1uF/25V  [C0402]  218.56 167.82 0 bottom
C2752  0.1uF/25V  [C0402]  217.23 200.15 90 top
C2753  0.1uF/25V  [C0402]  181.53 140.83 0 bottom
C2754  1uF/25V  [C0402]  187.53 121.84 0 bottom
C2755  47uF/6.3V  [C0805]  143.57 161.29 180 top
C2756  47uF/6.3V  [C0805]  143.57 156.72 180 top
C2757  22uF/6.3V  [C0603]  240.22 124.08 270 top
C2758  0.1uF/25V  [C0402]  201.54 123.83 180 bottom
C2759  47uF/6.3V  [C0805]  142.81 140.59 180 top
C2760  10uF/6.3V  [C0402]  207.55 147.82 0 bottom
C2761  47uF/6.3V  [C0805]  143.57 172.72 180 top
C2762  0.1uF/25V  [C0402]  198.03 170.33 270 bottom
C2763  22uF/6.3V  [C0603]  187.52 192.4 270 top
C2764  0.1uF/25V  [C0402]  211.57 152.85 0 bottom
C2765  1uF/25V  [C0402]  189.05 156.33 270 bottom
C2766  0.1uF/25V  [C0402]  225.51 140.84 180 bottom
C2767  0.1uF/25V  [C0402]  165.54 109.85 0 bottom
C2768  47uF/6.3V  [C0805]  143.57 168.15 180 top
C2769  0.1uF/25V  [C0402]  185.55 125.83 0 bottom
C2770  0.1uF/25V  [C0402]  205.07 170.33 270 bottom
C2771  0.1uF/25V  [C0402]  152.44 153.67 90 top
C2772  10uF/6.3V  [C0402]  205.55 137.82 0 bottom
C2774  1uF/25V  [C0402]  191.56 121.85 180 bottom
C2775  10uF/6.3V  [C0402]  199.54 141.83 0 bottom
C2776  0.1uF/25V  [C0402]  166.43 185.29 270 top
C2777  0.1uF/25V  [C0402]  213.55 133.82 0 bottom
C2778  0.1uF/25V  [C0402]  185.05 154.33 90 bottom
C2779  0.1uF/25V  [C0402]  159.83 185.8 270 top
C2780  0.1uF/25V  [C0402]  181.55 135.86 0 bottom
C2781  0.1uF/25V  [C0402]  151.22 153.67 90 top
C2782  0.1uF/25V  [C0402]  218.56 168.86 0 bottom
C2783  0.1uF/25V  [C0402]  230.54 162.76 0 bottom
C2784  10uF/6.3V  [C0402]  143.32 98.17 180 top
C2785  22uF/6.3V  [C0603]  240.22 162.3 270 top
C2786  0.1uF/25V  [C0402]  192.21 98.42 0 top
C2787  0.1uF/25V  [C0402]  215.55 119.81 180 bottom
C2788  10uF/6.3V  [C0402]  207.55 127.82 0 bottom
C2789  10uF/6.3V  [C0402]  143.32 95.88 180 top
C2790  10uF/6.3V  [C0402]  143.32 93.6 180 top
C2791  1uF/25V  [C0402]  181.53 121.84 0 bottom
C2792  10uF/6.3V  [C0402]  143.32 100.45 180 top
C2793  0.1uF/25V  [C0402]  217.54 160.85 180 bottom
C2794  0.1uF/25V  [C0402]  186.05 154.33 90 bottom
C2795  0.1uF/25V  [C0402]  213.55 127.82 0 bottom
C2796  47uF/6.3V  [C0805]  143.57 163.57 180 top
C2797  47uF/6.3V  [C0805]  143.57 159 180 top
C2798  0.1uF/25V  [C0402]  228.56 156.89 180 bottom
C2800  10uF/6.3V  [C0402]  199.54 134.83 0 bottom
C2801  22uF/6.3V  [C0603]  154.88 133.09 270 top
C2802  10uF/6.3V  [C0402]  205.55 145.82 0 bottom
C2803  10uF/6.3V  [C0402]  203.54 137.83 0 bottom
C2804  47uF/6.3V  [C0805]  257.11 113.79 0 top
C2805  0.1uF/25V  [C0402]  211.58 153.85 0 bottom
C2806  22uF/6.3V  [C0603]  231.46 173.35 270 bottom
C2807  103  [C0402]  155.51 141.6 0 top
C2808  0.1uF/25V  [C0402]  172.4 185.29 270 top
C2810  47uF/6.3V  [C0805]  226.38 183.61 90 top
C2811  47uF/6.3V  [C0805]  221.81 183.64 90 top
C2812  0.1uF/25V  [C0402]  168.56 152.82 0 bottom
C2813  47uF/6.3V  [C0805]  217.23 183.64 90 top
C2814  10uF/6.3V  [C0402]  203.54 127.83 0 bottom
C2815  0.1uF/25V  [C0402]  207.55 124.82 0 bottom
C2816  0.1uF/25V  [C0402]  227.53 127.83 0 bottom
C2817  10uF/6.3V  [C0402]  207.55 134.82 0 bottom
C2818  0.1uF/25V  [C0402]  208.06 166.34 90 bottom
C2819  0.1uF/25V  [C0402]  181.53 145.83 0 bottom
C2821  0.1uF/25V  [C0402]  207.71 200.15 90 top
C2823  10uF/6.3V  [C0402]  226.38 187.83 270 top
C2824  0.1uF/25V  [C0402]  211.08 162.35 90 bottom
C2825  10uF/6.3V  [C0402]  211.55 127.82 0 bottom
C2826  10uF/6.3V  [C0402]  252.67 132.08 180 top
C2827  0.1uF/25V  [C0402]  175.55 154.84 0 bottom
C2828  10uF/6.3V  [C0402]  207.55 130.82 0 bottom
C2829  10uF/6.3V  [C0402]  252.67 127.51 180 top
C2830  47uF/6.3V  [C0805]  224.09 183.61 90 top
C2831  0.1uF/25V  [C0402]  239.33 145.54 90 top
C2832  22uF/6.3V  [C0603]  157.16 133.09 270 top
C2834  47uF/6.3V  [C0805]  219.52 183.64 90 top
C2835  47uF/6.3V  [C0805]  204.03 185.54 90 top
C2836  10uF/6.3V  [C0402]  199.54 148.83 0 bottom
C2837  10uF/6.3V  [C0402]  207.55 146.82 0 bottom
C2838  10uF/6.3V  [C0402]  201.54 146.83 0 bottom
C2839  0.1uF/25V  [C0402]  205.05 165.34 90 bottom
C2840  22uF/6.3V  [C0603]  171.39 191.64 90 top
C2841  0.1uF/25V  [C0402]  209.57 152.85 0 bottom
C2842  0.1uF/25V  [C0402]  175.32 178.43 270 top
C2843  0.1uF/25V  [C0402]  205.04 96.14 0 top
C2844  103  [C0402]  155.51 142.62 0 top
C2845  0.1uF/25V  [C0402]  237.3 157.86 90 top
C2846  0.1uF/25V  [C0402]  230.58 146.83 0 bottom
C2847  47uF/6.3V  [C0805]  208.6 185.54 90 top
C2848  10uF/6.3V  [C0402]  199.54 132.83 0 bottom
C2849  0.1uF/25V  [C0402]  225.54 150.85 180 bottom
C2850  0.1uF/25V  [C0402]  168.56 113.85 0 bottom
C2851  10uF/6.3V  [C0402]  199.54 136.83 180 bottom
C2852  0.1uF/25V  [C0402]  181.55 129.85 180 bottom
C2853  0.1uF/25V  [C0402]  213.55 136.82 0 bottom
C2854  103  [C0402]  181.55 191.13 270 top
C2855  0.1uF/25V  [C0402]  177.23 98.42 0 top
C2856  0.1uF/25V  [C0402]  229.56 107.83 0 bottom
C2857  0.1uF/25V  [C0402]  207.57 154.85 0 bottom
C2858  22uF/6.3V  [C0603]  216.34 101.22 180 top
C2859  10uF/6.3V  [C0402]  203.54 129.83 0 bottom
C2860  0.1uF/25V  [C0402]  183.2 198.25 90 top
C2861  10uF/6.3V  [C0402]  252.67 122.93 180 top
C2862  47uF/6.3V  [C0805]  224.09 187.88 270 top
C2863  0.1uF/25V  [C0402]  225.54 166.9 180 bottom
C2864  47uF/6.3V  [C0805]  219.52 187.96 270 top
C2865  0.1uF/25V  [C0402]  238.7 157.86 90 top
C2866  0.1uF/25V  [C0402]  165.54 138.82 0 bottom
C2867  47uF/6.3V  [C0805]  228.66 187.88 270 top
C2868  0.1uF/25V  [C0402]  211.14 200.15 90 top
C2869  0.1uF/25V  [C0402]  213.03 171.36 90 bottom
C2870  10uF/6.3V  [C0402]  203.54 132.83 0 bottom
C2871  47uF/6.3V  [C0805]  252.67 120.65 180 top
C2872  0.1uF/25V  [C0402]  203.54 152.83 180 bottom
C2874  10uF/6.3V  [C0402]  207.55 145.82 0 bottom
C2875  10uF/6.3V  [C0402]  207.55 148.82 0 bottom
C2876  47uF/6.3V  [C0805]  252.67 116.08 180 top
C2877  0.1uF/25V  [C0402]  213.55 129.82 0 bottom
C2879  10uF/6.3V  [C0402]  209.55 151.82 0 bottom
C2880  0.1uF/25V  [C0402]  230.54 160.88 0 bottom
C2881  10uF/6.3V  [C0402]  147.64 109.6 0 top
C2882  47uF/6.3V  [C0805]  147.64 107.31 0 top
C2883  0.1uF/25V  [C0402]  203.05 164.32 90 bottom
C2884  0.1uF/25V  [C0402]  168.53 143.84 0 bottom
C2886  10uF/6.3V  [C0402]  207.55 132.82 0 bottom
C2887  0.1uF/25V  [C0402]  207.55 125.82 0 bottom
C2888  10uF/6.3V  [C0402]  207.55 137.82 0 bottom
C2889  0.1uF/25V  [C0402]  228.55 168.91 180 bottom
C2892  103  [C0402]  180.53 191.13 270 top
C2893  47uF/6.3V  [C0805]  147.64 102.74 0 top
C2894  0.1uF/25V  [C0402]  195.55 126.83 0 bottom
C2895  10uF/6.3V  [C0402]  207.55 133.82 0 bottom
C2896  10uF/6.3V  [C0402]  205.55 129.82 0 bottom
C2897  0.1uF/25V  [C0402]  205.04 98.42 0 top
C2898  22uF/6.3V  [C0603]  157.16 119.12 270 top
C2899  0.1uF/25V  [C0402]  195.55 152.82 0 bottom
C2900  10uF/6.3V  [C0402]  185.54 141.83 180 bottom
C2901  0.1uF/25V  [C0402]  223.53 172.84 0 bottom
C2902  0.1uF/25V  [C0402]  218.53 163.83 0 bottom
C2903  0.1uF/25V  [C0402]  193.05 157.32 90 bottom
C2904  0.1uF/25V  [C0402]  218.55 171.83 0 bottom
C2905  47uF/6.3V  [C0805]  210.5 98.93 0 top
C2906  0.1uF/25V  [C0402]  194.07 171.35 90 bottom
C2907  0.1uF/25V  [C0402]  181.53 142.83 0 bottom
C2908  10uF/6.3V  [C0402]  201.54 135.83 0 bottom
C2909  47uF/6.3V  [C0805]  243.78 118.36 180 top
C2910  47uF/6.3V  [C0805]  243.78 113.79 180 top
C2911  0.1uF/25V  [C0402]  181.53 143.83 0 bottom
C2912  10uF/6.3V  [C0402]  201.54 136.83 180 bottom
C2913  10uF/6.3V  [C0402]  207.55 126.82 0 bottom
C2914  47uF/6.3V  [C0805]  157.8 104.9 0 top
C2915  47uF/6.3V  [C0805]  228.66 183.61 90 top
C2917  10uF/6.3V  [C0402]  203.54 135.83 0 bottom
C2918  0.1uF/25V  [C0402]  168.57 115.85 0 bottom
C2919  0.1uF/25V  [C0402]  205.04 100.71 0 top
C2920  10uF/6.3V  [C0402]  199.54 150.83 180 bottom
C2921  0.1uF/25V  [C0402]  230.06 171.32 90 bottom
C2922  47uF/6.3V  [C0805]  226.38 179.32 270 top
C2923  10uF/6.3V  [C0402]  205.55 126.82 0 bottom
C2924  0.1uF/25V  [C0402]  238.44 170.05 90 top
C2925  0.1uF/25V  [C0402]  189.55 125.83 0 bottom
C2926  10uF/6.3V  [C0402]  248.22 116.08 0 top
C2927  0.1uF/25V  [C0402]  191.55 152.82 180 bottom
C2928  103  [C0402]  155.51 153.16 0 top
C2929  22uF/6.3V  [C0603]  217.23 192.66 270 top
C2930  10uF/6.3V  [C0402]  201.54 134.83 0 bottom
C2931  0.1uF/25V  [C0402]  230.54 166.85 0 bottom
C2932  22uF/6.3V  [C0603]  237.93 124.08 270 top
C2933  0.1uF/25V  [C0402]  199.54 127.83 0 bottom
C2934  10uF/6.3V  [C0402]  153.48 107.19 180 top
C2935  0.1uF/25V  [C0402]  221.54 164.82 0 bottom
C2936  10uF/6.3V  [C0402]  199.54 129.83 0 bottom
C2937  47uF/6.3V  [C0805]  148.02 172.72 0 top
C2938  0.1uF/25V  [C0402]  211.03 165.32 270 bottom
C2939  0.1uF/25V  [C0402]  165.53 133.85 0 bottom
C2940  22uF/6.3V  [C0603]  224.47 192.66 270 top
C2941  47uF/6.3V  [C0805]  206.31 185.54 90 top
C2943  10uF/6.3V  [C0402]  201.54 142.83 0 bottom
C2944  0.1uF/25V  [C0402]  213.55 135.82 0 bottom
C2945  0.1uF/25V  [C0402]  189.55 152.82 0 bottom
C2946  10uF/6.3V  [C0402]  207.55 149.82 0 bottom
C2947  10uF/6.3V  [C0402]  193.55 148.82 0 bottom
C2948  47uF/6.3V  [C0805]  210.88 185.54 90 top
C2949  10uF/6.3V  [C0402]  199.54 135.83 0 bottom
C2950  47uF/6.3V  [C0805]  221.81 187.96 270 top
C2951  0.1uF/25V  [C0402]  178.57 126.85 0 bottom
C2952  0.1uF/25V  [C0402]  189.55 123.83 0 bottom
C2953  0.1uF/25V  [C0402]  201.54 125.83 0 bottom
C2954  10uF/6.3V  [C0402]  153.48 102.61 180 top
C2955  0.1uF/25V  [C0402]  168.53 137.85 0 bottom
C2956  0.1uF/25V  [C0402]  220.59 172.84 0 bottom
C2957  0.1uF/25V  [C0402]  151.63 127.25 90 top
C2958  22uF/6.3V  [C0603]  154.88 145.79 270 top
C2959  0.1uF/25V  [C0402]  213.55 147.82 0 bottom
C2960  47uF/6.3V  [C0805]  217.23 187.96 270 top
C2961  10uF/6.3V  [C0402]  205.55 133.82 0 bottom
C2962  0.1uF/25V  [C0402]  210.99 170.33 270 bottom
C2963  10uF/6.3V  [C0402]  157.8 109.47 0 top
C2964  47uF/6.3V  [C0805]  230.95 187.88 270 top
C2965  10uF/6.3V  [C0402]  193.55 131.83 0 bottom
C2966  10uF/6.3V  [C0402]  221.81 179.32 270 top
C2967  0.1uF/25V  [C0402]  219.54 160.85 180 bottom
C2968  0.1uF/25V  [C0402]  172.56 143.84 0 bottom
C2969  22uF/6.3V  [C0603]  184.47 98.93 180 top
C2970  10uF/6.3V  [C0402]  205.55 130.82 0 bottom
C2971  0.1uF/25V  [C0402]  190.05 158.33 90 bottom
C2972  0.1uF/25V  [C0402]  173.55 148.83 0 bottom
C2973  0.1uF/25V  [C0402]  172.56 145.82 0 bottom
C2974  0.1uF/25V  [C0402]  200.06 164.35 270 bottom
C2975  0.1uF/25V  [C0402]  165.56 119.85 0 bottom
C2976  0.1uF/25V  [C0402]  168.56 150.85 0 bottom
C2977  0.1uF/25V  [C0402]  211.55 124.82 0 bottom
C2978  47uF/6.3V  [C0805]  252.67 118.36 180 top
C2979  0.1uF/25V  [C0402]  165.54 160.83 0 bottom
C2980  0.1uF/25V  [C0402]  173.55 151.85 0 bottom
C2981  0.1uF/25V  [C0402]  213.55 143.82 0 bottom
C2982  10uF/6.3V  [C0402]  187.54 143.83 0 bottom
C2983  47uF/6.3V  [C0805]  252.67 113.79 180 top
C2984  22uF/6.3V  [C0603]  164.66 185.29 90 top
C2985  10uF/6.3V  [C0402]  205.55 146.82 0 bottom
C2986  47uF/6.3V  [C0805]  147.64 105.03 0 top
C2987  0.1uF/25V  [C0402]  229.3 200.15 90 top
C2988  10uF/6.3V  [C0402]  203.54 134.83 0 bottom
C2989  10uF/6.3V  [C0402]  224.09 179.32 270 top
C2991  22uF/6.3V  [C0603]  208.72 192.66 270 top
C2992  0.1uF/25V  [C0402]  228.59 158.82 180 bottom
C2993  0.1uF/25V  [C0402]  181.55 128.85 0 bottom
C2994  47uF/6.3V  [C0805]  210.5 101.22 0 top
C2995  0.1uF/25V  [C0402]  225.56 168.83 180 bottom
C2996  0.1uF/25V  [C0402]  183.55 124.83 0 bottom
C2997  0.1uF/25V  [C0402]  235.9 157.86 90 top
C2998  10uF/6.3V  [C0402]  209.55 127.82 0 bottom
C2999  47uF/6.3V  [C0805]  210.5 96.64 0 top
C3000  47uF/6.3V  [C0805]  243.78 116.08 180 top
C3001  0.1uF/25V  [C0402]  223.96 96.14 0 top
C3002  0.1uF/25V  [C0402]  213.57 110.84 0 bottom
C3003  10uF/6.3V  [C0402]  199.54 140.83 0 bottom
C3004  10uF/6.3V  [C0402]  252.67 134.36 180 top
C3005  47uF/6.3V  [C0805]  157.8 107.19 0 top
C3006  0.1uF/25V  [C0402]  141.77 156.51 90 bottom
C3007  0.1uF/25V  [C0402]  168.03 146.31 270 bottom
C3008  22uF/6.3V  [C0603]  240.22 137.79 270 top
C3009  10uF/6.3V  [C0402]  201.54 137.83 0 bottom
C3010  22uF/6.3V  [C0603]  176.59 185.29 90 top
C3011  0.1uF/25V  [C0402]  179.56 117.87 0 bottom
C3012  0.1uF/25V  [C0402]  195.55 153.82 180 bottom
C3013  0.1uF/25V  [C0402]  165.53 140.83 0 bottom
C3014  0.1uF/25V  [C0402]  213.55 150.82 180 bottom
C3015  22uF/6.3V  [C0603]  150.41 145.23 270 bottom
C3016  0.1uF/25V  [C0402]  174.64 139.73 0 bottom
C3018  0.1uF/25V  [C0402]  209.05 170.38 270 bottom
C3019  0.1uF/25V  [C0402]  195.55 156.82 180 bottom
C3020  10uF/6.3V  [C0402]  185.54 142.83 0 bottom
C3021  1uF/25V  [C0402]  203.54 123.83 0 bottom
C3022  47uF/6.3V  [C0805]  157.8 102.61 0 top
C3023  0.1uF/25V  [C0402]  175.55 148.85 0 bottom
C3024  0.1uF/25V  [C0402]  195.55 124.83 0 bottom
C3025  10uF/6.3V  [C0402]  205.55 143.82 0 bottom
C3026  0.1uF/25V  [C0402]  193.53 107.84 0 bottom
C3027  0.1uF/25V  [C0402]  177.56 151.82 0 bottom
C3028  22uF/6.3V  [C0603]  237.93 150.11 270 top
C3029  0.1uF/25V  [C0402]  199.54 125.83 180 bottom
C3030  0.1uF/25V  [C0402]  177.23 100.71 0 top
C3031  0.1uF/25V  [C0402]  182.05 107.36 90 bottom
C3033  0.1uF/25V  [C0402]  225.56 164.81 180 bottom
C3034  0.1uF/25V  [C0402]  211.58 154.85 0 bottom
C3035  10uF/6.3V  [C0402]  252.67 129.79 180 top
C3036  1uF/25V  [C0402]  209.56 154.85 180 bottom
C3037  10uF/6.3V  [C0402]  252.67 125.22 180 top
C3039  10uF/6.3V  [C0402]  189.55 136.83 0 bottom
C3040  0.1uF/25V  [C0402]  230.49 164.87 0 bottom
C3041  22uF/6.3V  [C0603]  169.48 98.93 180 top
C3042  0.1uF/25V  [C0402]  179.55 154.85 0 bottom
C3043  22uF/6.3V  [C0603]  165.29 191.64 90 top
C3044  1uF/25V  [C0402]  199.56 120.84 0 bottom
C3045  10uF/6.3V  [C0402]  207.55 128.82 0 bottom
C3046  0.1uF/25V  [C0402]  171.54 148.85 180 bottom
C3047  0.1uF/25V  [C0402]  183.53 123.84 180 bottom
C3048  0.1uF/25V  [C0402]  168.57 148.85 0 bottom
C3050  0.1uF/25V  [C0402]  215.02 171.35 90 bottom
C3051  0.1uF/25V  [C0402]  159.65 140.07 90 top
C3052  0.1uF/25V  [C0402]  213.55 149.82 180 bottom
C3053  47uF/6.3V  [C0805]  230.95 183.61 90 top
C3054  0.1uF/25V  [C0402]  203.54 124.83 0 bottom
C3055  22uF/6.3V  [C0603]  170.5 185.29 90 top
C3056  10uF/6.3V  [C0402]  183.54 142.83 0 bottom
C3057  47uF/6.3V  [C0805]  161.86 100.2 270 top
C3058  0.1uF/25V  [C0402]  214.82 200.15 90 top
C3059  0.1uF/25V  [C0402]  165.54 168.86 0 bottom
C3060  47uF/6.3V  [C0805]  164.15 100.2 270 top
C3061  0.1uF/25V  [C0402]  240.73 145.54 90 top
C3062  0.1uF/25V  [C0402]  165.53 131.85 180 bottom
C3063  10uF/6.3V  [C0402]  207.55 143.82 0 bottom
C3065  0.1uF/25V  [C0402]  185.53 110.84 180 bottom
C3066  0.1uF/25V  [C0402]  173.29 190.88 270 top
C3067  1uF/25V  [C0402]  179.54 116.84 0 bottom
C3068  22uF/6.3V  [C0603]  166.43 179.07 90 top
C3069  0.1uF/25V  [C0402]  181.55 131.85 0 bottom
C3070  47uF/6.3V  [C0805]  143.32 121.03 180 top
C3071  10uF/6.3V  [C0402]  147.64 111.88 0 top
C3072  47uF/6.3V  [C0805]  143.32 116.46 180 top
C3073  0.1uF/25V  [C0402]  166.56 150.86 0 bottom
C3074  0.1uF/25V  [C0402]  201.05 167.33 90 bottom
C3075  10uF/6.3V  [C0402]  147.64 114.17 0 top
C3076  0.1uF/25V  [C0402]  226.89 173.45 90 bottom
C3077  22uF/6.3V  [C0603]  197.29 98.93 180 top
C3078  47uF/6.3V  [C0805]  143.32 111.88 180 top
C3079  1uF/25V  [C0402]  179.53 111.86 180 bottom
C3080  10uF/6.3V  [C0402]  195.55 135.83 0 bottom
C3081  0.1uF/25V  [C0402]  177.56 148.85 0 bottom
C3082  0.1uF/25V  [C0402]  221.54 160.85 180 bottom
C3083  22uF/6.3V  [C0603]  179.39 179.07 90 top
C3084  0.1uF/25V  [C0402]  185.61 199.26 90 bottom
C3085  0.1uF/25V  [C0402]  175.55 151.85 0 bottom
C3086  0.1uF/25V  [C0402]  165.56 156.83 0 bottom
C3087  0.1uF/25V  [C0402]  179.53 112.86 180 bottom
C3088  10uF/6.3V  [C0402]  183.54 143.83 180 bottom
C3089  0.1uF/25V  [C0402]  180.07 107.33 270 bottom
C3090  0.1uF/25V  [C0402]  177.53 143.84 0 bottom
C3091  10uF/6.3V  [C0402]  191.55 146.82 0 bottom
C3092  0.1uF/25V  [C0402]  181.55 132.84 180 bottom
C3093  47uF/6.3V  [C0805]  143.32 107.31 180 top
C3094  0.1uF/25V  [C0402]  223.54 160.85 180 bottom
C3095  0.1uF/25V  [C0402]  239.51 116.28 90 top
C3096  22uF/6.3V  [C0603]  158.81 131.95 270 bottom
C3097  22uF/6.3V  [C0603]  237.93 162.3 270 top
C3098  47uF/6.3V  [C0805]  143.32 102.74 180 top
C3099  22uF/6.3V  [C0603]  197.29 101.22 180 top
C3100  0.1uF/25V  [C0402]  171.54 146.83 0 bottom
C3101  0.1uF/25V  [C0402]  168.56 164.85 0 bottom
C3103  0.1uF/25V  [C0402]  168.54 142.82 0 bottom
C3104  0.1uF/25V  [C0402]  213.55 141.82 0 bottom
C3105  10uF/6.3V  [C0402]  248.22 118.36 0 top
C3106  22uF/6.3V  [C0603]  211.14 192.66 270 top
C3107  0.1uF/25V  [C0402]  192.21 100.71 0 top
C3108  103  [C0402]  245.55 153.16 270 top
C3109  0.1uF/25V  [C0402]  227.52 140.84 0 bottom
C3110  10uF/6.3V  [C0402]  185.55 133.83 0 bottom
C3111  0.1uF/25V  [C0402]  191.55 125.83 0 bottom
C3112  0.1uF/25V  [C0402]  187.53 120.84 0 bottom
C3113  0.1uF/25V  [C0402]  165.54 148.84 180 bottom
C3114  0.1uF/25V  [C0402]  205.55 125.82 0 bottom
C3115  0.1uF/25V  [C0402]  227.04 171.36 270 bottom
C3116  0.1uF/25V  [C0402]  183.05 154.33 270 bottom
C3117  0.1uF/25V  [C0402]  181.52 170.85 0 bottom
C3119  47uF/6.3V  [C0805]  143.57 148.71 180 top
C3120  0.1uF/25V  [C0402]  170.53 143.82 0 bottom
C3121  0.1uF/25V  [C0402]  207.57 152.85 180 bottom
C3122  0.1uF/25V  [C0402]  154.5 175.89 180 top
C3123  0.1uF/25V  [C0402]  209.55 125.82 0 bottom
C3124  0.1uF/25V  [C0402]  165.54 146.81 0 bottom
C3125  0.1uF/25V  [C0402]  165.53 142.86 0 bottom
C3126  10uF/6.3V  [C0402]  199.54 144.83 0 bottom
C3127  10uF/6.3V  [C0402]  248.22 113.79 0 top
C3128  0.1uF/25V  [C0402]  240.73 131.82 90 top
C3130  0.1uF/25V  [C0402]  214.08 158.34 90 bottom
C3131  47uF/6.3V  [C0805]  143.57 146.43 180 top
C3132  0.1uF/25V  [C0402]  216.06 167.36 90 bottom
C3133  0.1uF/25V  [C0402]  193.53 106.84 0 bottom
C3134  0.1uF/25V  [C0402]  203.06 154.35 90 bottom
C3136  10uF/6.3V  [C0402]  153.48 104.9 180 top
C3137  22uF/6.3V  [C0603]  154.88 119.12 270 top
C3138  0.1uF/25V  [C0402]  168.57 127.83 0 bottom
C3139  47uF/6.3V  [C0805]  257.11 164.08 0 top
C3140  0.1uF/25V  [C0402]  176.57 145.84 0 bottom
C3141  0.1uF/25V  [C0402]  179.52 170.85 180 bottom
C3142  103  [C0402]  246.7 153.16 270 top
C3143  47uF/6.3V  [C0805]  257.11 159.51 0 top
C3144  0.1uF/25V  [C0402]  209.04 168.37 90 bottom
C3145  0.1uF/25V  [C0402]  174.56 145.82 0 bottom
C3146  10uF/6.3V  [C0402]  193.55 129.83 0 bottom
C3147  0.1uF/25V  [C0402]  218.56 165.86 0 bottom
C3150  0.1uF/25V  [C0402]  239.97 170.05 90 top
C3151  0.1uF/25V  [C0402]  185.55 124.83 0 bottom
C3152  0.1uF/25V  [C0402]  179.05 160.33 90 bottom
C3153  0.1uF/25V  [C0402]  203.05 167.31 270 bottom
C3154  0.1uF/25V  [C0402]  175.55 142.85 0 bottom
C3155  0.1uF/25V  [C0402]  213.55 140.82 0 bottom
C3156  0.1uF/25V  [C0402]  181.55 134.87 0 bottom
C3157  10uF/6.3V  [C0402]  203.54 131.83 0 bottom
C3158  0.1uF/25V  [C0402]  186.56 167.84 180 bottom
C3159  47uF/6.3V  [C0805]  257.11 154.94 0 top
C3160  47uF/6.3V  [C0805]  257.11 150.37 0 top
C3161  47uF/6.3V  [C0805]  257.11 143.51 0 top
C3162  22uF/6.3V  [C0603]  222.06 192.66 270 top
C3163  47uF/6.3V  [C0805]  257.11 138.94 0 top
C3164  22uF/6.3V  [C0603]  216.34 96.64 180 top
C3166  0.1uF/25V  [C0402]  181.54 148.83 0 bottom
C3167  47uF/6.3V  [C0805]  257.11 134.36 0 top
C3169  10uF/6.3V  [C0402]  157.8 111.76 0 top
C3170  10uF/6.3V  [C0402]  219.52 179.32 270 top
